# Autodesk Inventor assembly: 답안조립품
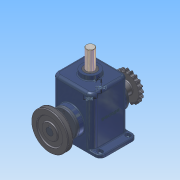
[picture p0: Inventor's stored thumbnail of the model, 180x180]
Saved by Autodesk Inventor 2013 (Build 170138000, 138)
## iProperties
Created: 2015-03
Part Number: 답안조립품
Document SubType Name: Assembly
Designer: Administrator
Mass: 8579 g
Surface Area: 4386.44 cm^2
Volume: 1982.5 cm^3
Density: 4.32736 g/cm^3
Author: Administrator
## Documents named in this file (15)
- C:\Documents and Settings\Administrator\바탕 화면\350305V1013\답안조립품.iam
- C:\Documents and Settings\Administrator\바탕 화면\350305V1013\본체.ipt
- C:\Documents and Settings\Administrator\바탕 화면\350305V1013\베어링 6205.ipt
- C:\Documents and Settings\Administrator\바탕 화면\350305V1013\편심축.ipt
- C:\Documents and Settings\Administrator\바탕 화면\350305V1013\커버.ipt
- C:\Documents and Settings\Administrator\바탕 화면\350305V1013\M4x0.5.ipt
- C:\Documents and Settings\Administrator\바탕 화면\350305V1013\오일실.ipt
- C:\Documents and Settings\Administrator\바탕 화면\350305V1013\키 8x8.ipt
- C:\Documents and Settings\Administrator\바탕 화면\350305V1013\체인 스프로킷.ipt
- C:\Documents and Settings\Administrator\바탕 화면\350305V1013\멈춤나사 M5x0.5.ipt
- C:\Documents and Settings\Administrator\바탕 화면\350305V1013\멈춤링.ipt
- C:\Documents and Settings\Administrator\바탕 화면\350305V1013\V-벨트풀리.ipt
- C:\Documents and Settings\Administrator\바탕 화면\350305V1013\부시.ipt
- C:\Documents and Settings\Administrator\바탕 화면\350305V1013\슬라이드.ipt
- C:\Documents and Settings\Administrator\바탕 화면\350305V1013\가변스프링.ipt
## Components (9 placed, 4 different names)
1. 5-체인 스프로킷:1 — 플러쉬:2, 각도:2
2. V-벨트풀리:1 — 플러쉬:4, 각도:4
3. 가변스프링:1
4. M4x0.5:1
5. M4x0.5:2
6. M4x0.5:3
7. M4x0.5:4
8. M4x0.5:5
9. M4x0.5:6
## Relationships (4: Flush 2, Angle 2)
- 플러쉬:2 [Flush]: 5-체인 스프로킷:1
- 각도:2 [Angle]: 5-체인 스프로킷:1
- 플러쉬:4 [Flush]: V-벨트풀리:1
- 각도:4 [Angle]: V-벨트풀리:1
